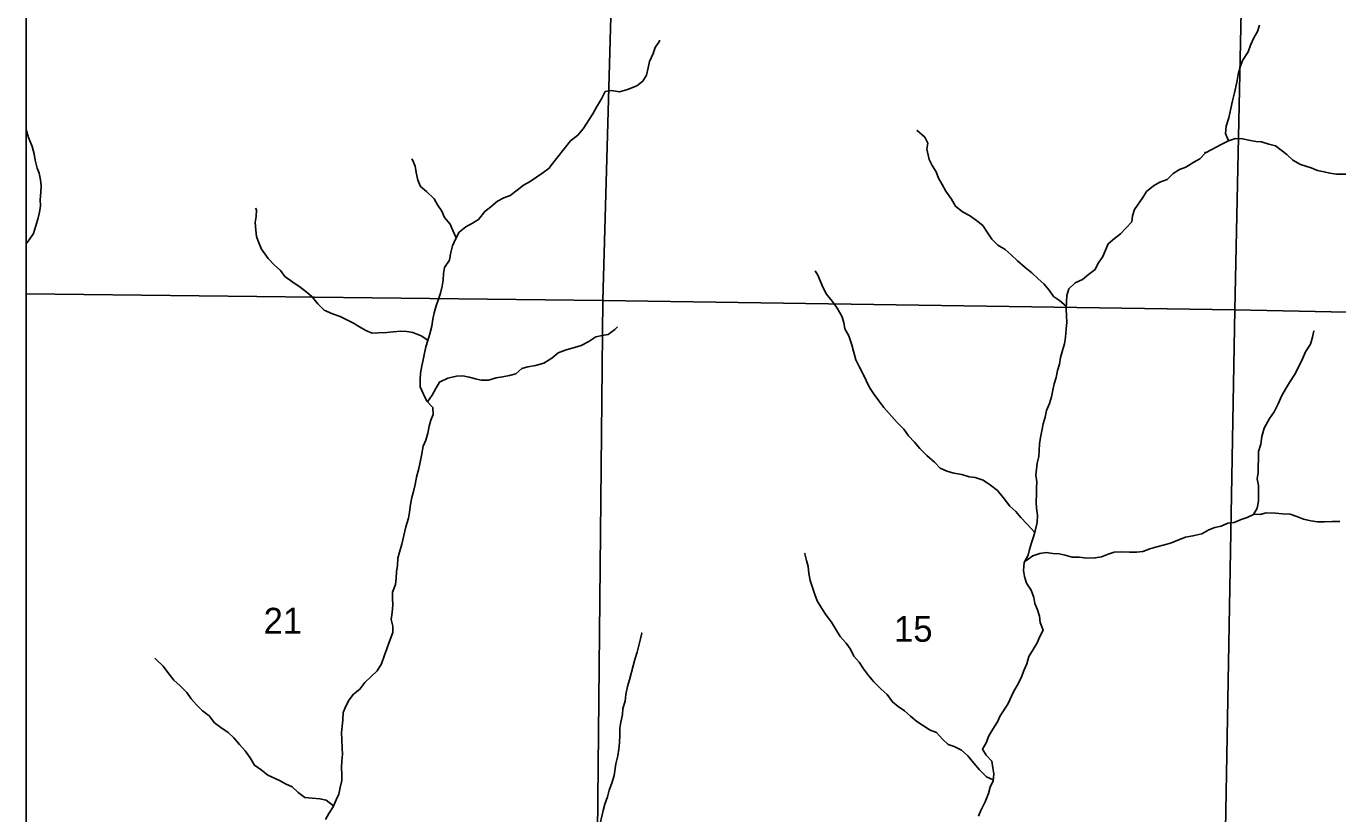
# Model space of a CAD drawing. Extents: x -10 to 158, y 8 to 33.
# Drawn here: x 37.524 to 39.647, y 17.962 to 19.238 of the extents above; entities that cross this region are included whole.
import ezdxf

# ---------------------------------------------------------------- set-up
doc = ezdxf.new("R2010")
doc.units = 0
for name, color, linetype in [('GM_X_Corporation', 7, 'Continuous'), ('GM_X_Minor_River', 7, 'Continuous'), ('GM_X_Section_Text', 7, 'Continuous')]:
    doc.layers.add(name, color=color, linetype=linetype)

msp = doc.modelspace()

# ---------------------------------------------------------------- linework, layer by layer
at = {"layer": 'GM_X_Corporation'}
for points in [[(37.524, 21.9552), (37.524, 15.7497), (37.7567, 15.7457), (37.7829, 15.7482), (38.4011, 15.7354), (38.4372, 15.735), (38.8933, 15.7292), (39.819, 15.7134), (40.6217, 15.6958), (40.9385, 15.6945), (41.0034, 15.692), (41.0879, 15.6892), (41.1505, 15.6889), (41.3714, 15.6858), (41.4556, 15.685), (41.4573, 15.7877), (41.458, 15.832), (41.4581, 15.8355), (41.4842, 16.8508), (41.4916, 17.5539), (41.5025, 18.3092), (41.5125, 19.0268), (41.5184, 19.3523)], [(37.524, 19.8122), (37.524, 15.7497), (37.7567, 15.7457), (37.7829, 15.7482), (38.4011, 15.7354), (38.4372, 15.735), (38.8933, 15.7292), (39.819, 15.7134), (40.6217, 15.6958), (40.9385, 15.6945), (41.0034, 15.692), (41.0879, 15.6892), (41.1505, 15.6889), (41.3714, 15.6858), (41.4556, 15.685), (41.4573, 15.7877), (41.458, 15.832), (41.4581, 15.8355), (41.4842, 16.8508), (41.4916, 17.5539), (41.5025, 18.3092), (41.5125, 19.0268), (41.5184, 19.3523)]]:
    msp.add_lwpolyline(points, dxfattribs=at)
for points in [[(37.524, 19.8135), (37.524, 18.8044), (38.4573, 18.7935), (38.486, 19.809)], [(39.5015, 19.7966), (39.4803, 18.7786), (38.4573, 18.7935), (38.486, 19.809)], [(40.5256, 19.7858), (40.494, 18.7574), (39.4803, 18.7786), (39.5015, 19.7966)], [(37.524, 18.8044), (37.524, 17.7838), (38.4469, 17.7694), (38.4573, 18.7935)], [(38.4573, 18.7935), (39.4803, 18.7786), (39.4619, 17.7563), (38.4469, 17.7694)], [(39.4803, 18.7786), (40.494, 18.7574), (40.4751, 17.7434), (39.4619, 17.7563)]]:
    msp.add_lwpolyline(points, close=True, dxfattribs=at)
at = {"layer": 'GM_X_Minor_River'}
for points in [[(39.4697, 19.0521), (39.465, 19.0641), (39.466, 19.0759), (39.4704, 19.0892), (39.4736, 19.1044), (39.4764, 19.1169), (39.4797, 19.1299), (39.4818, 19.1394), (39.484, 19.15), (39.4857, 19.1595), (39.489, 19.1713), (39.4926, 19.1823), (39.5016, 19.1961), (39.5056, 19.2068), (39.5111, 19.2186), (39.517, 19.2293), (39.5203, 19.2392)], [(38.3739, 19.0132), (38.405, 19.0521), (38.4167, 19.0613), (38.4252, 19.0717), (38.4408, 19.0958), (38.4471, 19.1065), (38.4553, 19.1203), (38.4612, 19.1317), (38.4714, 19.1334), (38.4843, 19.1313), (38.4972, 19.1349), (38.5123, 19.1412), (38.522, 19.1489), (38.528, 19.1585), (38.5308, 19.1703), (38.5326, 19.1805), (38.5389, 19.1935), (38.5422, 19.2034), (38.5488, 19.2137), (38.5488, 19.2153)], [(37.5418, 19.0077), (37.5386, 19.0207), (37.537, 19.0309), (37.5334, 19.043), (37.5275, 19.0577), (37.524, 19.0705)], [(38.9853, 19.0219), (38.9817, 19.0385), (38.9835, 19.0484), (38.9784, 19.0582), (38.9661, 19.0686), (38.9654, 19.0694)], [(39.5642, 19.0297), (39.546, 19.0438), (39.535, 19.0466), (39.5235, 19.0506), (39.5141, 19.0512), (39.503, 19.0533), (39.4928, 19.0554), (39.4814, 19.0556), (39.4697, 19.0521), (39.4592, 19.0466), (39.4325, 19.0327), (39.4313, 19.0337)], [(38.2197, 18.895), (38.2145, 18.9069), (38.2102, 18.9171), (38.201, 18.928), (38.1964, 18.9382), (38.1898, 18.9483), (38.1841, 18.9581), (38.1718, 18.9701), (38.1623, 18.9783), (38.158, 18.9885), (38.1553, 19.001), (38.1536, 19.0109), (38.149, 19.021), (38.1482, 19.0229)], [(39.2074, 18.7844), (39.1965, 18.7935), (39.1869, 18.7998), (39.1796, 18.8103), (39.1712, 18.8205), (39.1617, 18.8287), (39.1517, 18.838), (39.1407, 18.847), (39.1285, 18.8579), (39.1182, 18.8672), (39.1082, 18.8762), (39.0968, 18.8833), (39.0869, 18.8926), (39.0792, 18.9043), (39.0723, 18.9148), (39.062, 18.923), (39.0509, 18.9309), (39.0395, 18.9372), (39.0281, 18.9462), (39.0215, 18.9575), (39.0123, 18.9706), (39.0065, 18.9815), (39.0007, 18.9917), (38.9965, 19.0019), (38.9903, 19.0121), (38.9853, 19.0219), (38.9861, 19.0215)], [(39.2219, 18.8222), (39.2336, 18.8277), (39.2433, 18.8358), (39.2539, 18.8435), (39.2583, 18.853), (39.2665, 18.8649), (39.271, 18.8748), (39.2754, 18.8851), (39.2855, 18.8939), (39.2953, 18.9016), (39.3133, 18.9208), (39.3143, 18.9307), (39.3176, 18.9406), (39.331, 18.9605), (39.3374, 18.97), (39.3486, 18.9789), (39.3588, 18.9851), (39.3705, 18.9894), (39.3802, 18.999), (39.3904, 19.0056), (39.4009, 19.0095), (39.4137, 19.0173), (39.4235, 19.0231), (39.4325, 19.0327), (39.4325, 19.033)], [(39.5642, 19.0297), (39.5738, 19.0207), (39.5863, 19.0137), (39.6038, 19.0082), (39.614, 19.0038), (39.6247, 19.002), (39.6341, 18.9999), (39.6447, 18.9981), (39.6557, 18.9978), (39.6667, 18.998), (39.6784, 19.0004), (39.6908, 19.0047), (39.7026, 19.0037), (39.7131, 19.0099), (39.7241, 19.0127), (39.7369, 19.017), (39.7486, 19.0202), (39.7596, 19.0192), (39.7732, 19.0179), (39.7853, 19.0176), (39.7956, 19.0162), (39.8062, 19.0145), (39.8164, 19.0123), (39.8191, 19.0116)], [(37.524, 18.8853), (37.5285, 18.8918), (37.5356, 18.9021), (37.5389, 18.9128), (37.5426, 18.925), (37.5455, 18.9364), (37.5469, 18.9467), (37.5464, 18.9565), (37.5475, 18.9687), (37.5481, 18.9789), (37.5473, 18.9888), (37.5449, 18.9997), (37.5418, 19.0077)], [(38.0257, 17.9847), (38.0302, 17.9942), (38.032, 18.0049), (38.0349, 18.0163), (38.0348, 18.0258), (38.0343, 18.0364), (38.0349, 18.0482), (38.036, 18.0588), (38.0355, 18.0687), (38.0346, 18.0823), (38.0345, 18.0933), (38.0355, 18.1043), (38.0362, 18.1138), (38.0372, 18.126), (38.0413, 18.1363), (38.0468, 18.1466), (38.0539, 18.1561), (38.0641, 18.1638), (38.0719, 18.1746), (38.0824, 18.1846), (38.0922, 18.1938), (38.0992, 18.2053), (38.104, 18.219), (38.1077, 18.2293), (38.1114, 18.2399), (38.1173, 18.2556), (38.1172, 18.2658), (38.1148, 18.2771), (38.1162, 18.2882), (38.1172, 18.3003), (38.1167, 18.3113), (38.1166, 18.3212), (38.1214, 18.3334), (38.1228, 18.344), (38.1235, 18.3539), (38.1249, 18.3641), (38.1255, 18.3763), (38.1281, 18.3858), (38.1317, 18.3991), (38.135, 18.4128), (38.1386, 18.4269), (38.1427, 18.441), (38.1445, 18.4505), (38.1459, 18.463), (38.148, 18.4744), (38.1506, 18.4843), (38.1535, 18.4957), (38.1556, 18.5075), (38.1593, 18.5212), (38.1614, 18.5315), (38.1636, 18.5425), (38.1665, 18.5574), (38.1709, 18.5673), (38.1738, 18.5787), (38.176, 18.5897), (38.1789, 18.5996), (38.1826, 18.6091), (38.1821, 18.6201), (38.1726, 18.6306), (38.1672, 18.6416), (38.1614, 18.6536), (38.1616, 18.6654), (38.1623, 18.676), (38.1644, 18.6874), (38.1662, 18.6973), (38.1688, 18.708), (38.1709, 18.7182), (38.1739, 18.7289), (38.1772, 18.7396), (38.1804, 18.7517), (38.1822, 18.7631), (38.184, 18.7734), (38.1873, 18.7848), (38.1914, 18.7955), (38.1943, 18.8054), (38.1972, 18.8168), (38.1986, 18.8263), (38.1993, 18.8373), (38.2011, 18.8468), (38.2093, 18.8587), (38.2107, 18.8693), (38.214, 18.8819), (38.2191, 18.8941), (38.2247, 18.904), (38.2356, 18.9125), (38.2461, 18.9187), (38.2559, 18.9249), (38.2664, 18.9375), (38.2762, 18.9449), (38.2867, 18.9541), (38.2972, 18.9599), (38.3074, 18.9635), (38.3186, 18.9719), (38.3288, 18.98), (38.3397, 18.9862), (38.36, 19.0001), (38.3705, 19.0079), (38.3739, 19.0132)], [(38.174, 18.7294), (38.1632, 18.736), (38.1499, 18.7415), (38.14, 18.7433), (38.1302, 18.7439), (38.1181, 18.7426), (38.1079, 18.7417), (38.0939, 18.7412), (38.0841, 18.7403), (38.0738, 18.7451), (38.0635, 18.751), (38.0536, 18.7566), (38.0418, 18.7629), (38.0319, 18.7677), (38.0198, 18.7717), (38.0061, 18.778), (37.9958, 18.7881), (37.9862, 18.7998), (37.9767, 18.808), (37.9671, 18.8151), (37.9557, 18.8229), (37.9428, 18.8322), (37.9355, 18.842), (37.9252, 18.8513), (37.9156, 18.8615), (37.9048, 18.8765), (37.9002, 18.8867), (37.8967, 18.8969), (37.8955, 18.9075), (37.8946, 18.9196), (37.896, 18.9295), (37.8966, 18.9401), (37.8951, 18.9431)], [(39.1563, 18.4177), (39.1437, 18.4317), (39.1337, 18.4418), (39.1257, 18.4516), (39.1161, 18.4606), (39.105, 18.4745), (39.0962, 18.4857), (39.0848, 18.4943), (39.0726, 18.5025), (39.0597, 18.5069), (39.0502, 18.5079), (39.0384, 18.5116), (39.0252, 18.5141), (39.0138, 18.517), (39.0035, 18.5218), (38.9943, 18.5315), (38.9818, 18.5424), (38.9703, 18.554), (38.9619, 18.5638), (38.9519, 18.5743), (38.9446, 18.5852), (38.9339, 18.596), (38.9251, 18.6058), (38.9121, 18.62), (38.9037, 18.6309), (38.8964, 18.6415), (38.8887, 18.6524), (38.8833, 18.6641), (38.8786, 18.6739), (38.8725, 18.6856), (38.8667, 18.6972), (38.8628, 18.7112), (38.86, 18.7214), (38.8553, 18.7365), (38.8492, 18.7475), (38.8472, 18.7581), (38.844, 18.7683), (38.8363, 18.7811), (38.8287, 18.7924), (38.8195, 18.8036), (38.8141, 18.8142), (38.8098, 18.824), (38.8055, 18.8346), (38.8009, 18.8417)], [(39.0651, 17.9581), (39.0692, 17.9676), (39.0759, 17.9818), (39.0814, 17.9951), (39.0843, 18.0054), (39.0888, 18.0157), (39.0902, 18.0267), (39.0886, 18.0369), (39.0866, 18.0475), (39.0778, 18.0573), (39.0716, 18.0671), (39.0776, 18.077), (39.082, 18.0884), (39.0887, 18.0991), (39.0962, 18.111), (39.1002, 18.1209), (39.1125, 18.1396), (39.1222, 18.1595), (39.13, 18.174), (39.1348, 18.1839), (39.1392, 18.1953), (39.1437, 18.2053), (39.147, 18.2171), (39.154, 18.2285), (39.1604, 18.2392), (39.1648, 18.2495), (39.17, 18.2598), (39.1653, 18.2719), (39.1641, 18.2825), (39.161, 18.2923), (39.1563, 18.3025), (39.1547, 18.3127), (39.1504, 18.3241), (39.1431, 18.3357), (39.1396, 18.3463), (39.138, 18.3562), (39.139, 18.3691), (39.1457, 18.3809), (39.1479, 18.3904), (39.1512, 18.4011), (39.1548, 18.4125), (39.1578, 18.4228), (39.1603, 18.4338), (39.1609, 18.4456), (39.1593, 18.4573), (39.1588, 18.4675), (39.1591, 18.4797), (39.159, 18.4903), (39.1597, 18.4998), (39.158, 18.5108), (39.1591, 18.5203), (39.1605, 18.5298), (39.1627, 18.5408), (39.1637, 18.5507), (39.164, 18.5613), (39.1654, 18.5716), (39.1679, 18.5826), (39.1701, 18.5936), (39.173, 18.6047), (39.1755, 18.6153), (39.18, 18.6264), (39.1836, 18.6374), (39.1854, 18.6484), (39.188, 18.6583), (39.1909, 18.669), (39.1931, 18.68), (39.1964, 18.6903), (39.1981, 18.7013), (39.2014, 18.7123), (39.2044, 18.7234), (39.2061, 18.734), (39.2071, 18.7473), (39.2085, 18.7583), (39.2077, 18.7682), (39.2072, 18.7803), (39.2085, 18.8016), (39.2114, 18.8122), (39.2219, 18.8222)], [(38.1735, 18.6296), (38.1808, 18.6402), (38.1871, 18.6509), (38.1927, 18.6612), (38.2063, 18.6679), (38.2206, 18.6707), (38.2308, 18.6712), (38.2411, 18.6694), (38.2509, 18.6665), (38.2604, 18.6644), (38.2721, 18.6645), (38.2846, 18.6681), (38.2948, 18.6697), (38.3061, 18.6721), (38.3163, 18.6749), (38.3261, 18.6834), (38.3359, 18.6862), (38.3483, 18.6882), (38.3619, 18.6918), (38.3747, 18.7003), (38.3848, 18.7088), (38.398, 18.7135), (38.4116, 18.7171), (38.4222, 18.7206), (38.4346, 18.7268), (38.4459, 18.7345), (38.4561, 18.7369), (38.4659, 18.7386), (38.4768, 18.7463), (38.4809, 18.7509)], [(39.1401, 18.3709), (39.1533, 18.3802), (39.1646, 18.3838), (39.1748, 18.3851), (39.1854, 18.384), (39.1956, 18.3834), (39.2055, 18.3813), (39.2169, 18.3776), (39.2282, 18.3777), (39.2407, 18.376), (39.2543, 18.3765), (39.2645, 18.3786), (39.2751, 18.3829), (39.2849, 18.386), (39.2966, 18.3862), (39.3095, 18.3859), (39.3212, 18.3861), (39.3314, 18.387), (39.3428, 18.3913), (39.3541, 18.3945), (39.3661, 18.398), (39.3778, 18.4012), (39.388, 18.4051), (39.4005, 18.4102), (39.4122, 18.4122), (39.4265, 18.4158), (39.4382, 18.422), (39.448, 18.426), (39.4578, 18.428), (39.4687, 18.4327), (39.4793, 18.4339), (39.4902, 18.4386), (39.5004, 18.4421), (39.5106, 18.4468), (39.5162, 18.4571), (39.5187, 18.4685), (39.5185, 18.494), (39.5164, 18.5049), (39.5182, 18.5148), (39.5181, 18.5247), (39.5184, 18.5372), (39.5187, 18.549), (39.5223, 18.5608), (39.5241, 18.5733), (39.5277, 18.5866), (39.5363, 18.6023), (39.5438, 18.613), (39.5504, 18.626), (39.5564, 18.6397), (39.5623, 18.65), (39.5686, 18.6607), (39.5765, 18.6729), (39.5843, 18.6878), (39.5898, 18.6989), (39.5943, 18.7103), (39.6028, 18.723), (39.6061, 18.734), (39.6083, 18.7443), (39.6079, 18.7443)], [(39.5108, 18.4473), (39.5212, 18.447), (39.531, 18.4497), (39.5461, 18.4492), (39.5571, 18.4478), (39.5696, 18.4472), (39.5806, 18.4435), (39.5913, 18.4395), (39.6034, 18.4366), (39.614, 18.4348), (39.6254, 18.435), (39.6375, 18.4355), (39.6503, 18.4353)], [(39.089, 18.0174), (39.0781, 18.022), (39.0667, 18.0336), (39.0575, 18.0441), (39.0479, 18.0561), (39.038, 18.0655), (39.0258, 18.071), (39.0163, 18.0743), (39.0068, 18.0833), (38.9972, 18.0938), (38.9873, 18.0979), (38.9763, 18.1046), (38.9656, 18.1117), (38.9553, 18.1203), (38.9454, 18.1289), (38.9355, 18.1359), (38.9259, 18.1434), (38.9175, 18.1554), (38.9079, 18.1641), (38.8961, 18.1757), (38.8873, 18.1862), (38.8789, 18.1971), (38.8723, 18.208), (38.8635, 18.2177), (38.8581, 18.2287), (38.8512, 18.2388), (38.8416, 18.2493), (38.8339, 18.2618), (38.8274, 18.2727), (38.8186, 18.284), (38.8117, 18.2949), (38.804, 18.3069), (38.8005, 18.3175), (38.797, 18.3273), (38.793, 18.3402), (38.7907, 18.3515), (38.7894, 18.3625), (38.7867, 18.3723), (38.7843, 18.3833), (38.7847, 18.3844)], [(38.4522, 17.9445), (38.4577, 17.9673), (38.4606, 17.9776), (38.465, 17.9898), (38.4676, 18.0004), (38.472, 18.0119), (38.4757, 18.0244), (38.4785, 18.0431), (38.4814, 18.056), (38.4832, 18.067), (38.4842, 18.0777), (38.4845, 18.0894), (38.4847, 18.1008), (38.4862, 18.1107), (38.4891, 18.1229), (38.4897, 18.1327), (38.4934, 18.1445), (38.4944, 18.1555), (38.4973, 18.1685), (38.5002, 18.1791), (38.5061, 18.202), (38.509, 18.2119), (38.513, 18.2237), (38.5156, 18.2347), (38.5181, 18.2454), (38.5203, 18.2549), (38.5195, 18.2549)], [(38.0214, 17.975), (38.0095, 17.9841), (37.9992, 17.9866), (37.9867, 17.9876), (37.975, 17.9886), (37.9643, 17.9968), (37.9544, 18.0058), (37.9437, 18.0106), (37.9339, 18.0162), (37.9148, 18.025), (37.9042, 18.0332), (37.8935, 18.0407), (37.8862, 18.0531), (37.8785, 18.0644), (37.8689, 18.0745), (37.8601, 18.0854), (37.8506, 18.0936), (37.8392, 18.1018), (37.8289, 18.1097), (37.82, 18.1206), (37.8094, 18.1288), (37.7994, 18.1389), (37.791, 18.1486), (37.7837, 18.1584), (37.773, 18.1697), (37.7627, 18.1786), (37.7531, 18.191), (37.7454, 18.2015), (37.7348, 18.2113), (37.7321, 18.2143)], [(38.0083, 17.953), (38.0135, 17.9629), (38.0206, 17.9733), (38.0257, 17.9847)]]:
    msp.add_lwpolyline(points, dxfattribs=at)

# ---------------------------------------------------------------- texts
at = {"layer": 'GM_X_Section_Text'}
for s, p in [('21', (37.9082, 18.2539)), ('15', (38.9286, 18.2408))]:
    msp.add_text(s, height=0.04186, rotation=0, dxfattribs=at).set_placement(p)

doc.saveas('drawing.dxf')
